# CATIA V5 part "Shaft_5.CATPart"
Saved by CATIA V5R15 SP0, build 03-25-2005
Part number: Shaft_5
Bounding box of the stored display mesh (mm): x -23.8 to 23.8, y -23.8 to 23.8, z 0 to 395
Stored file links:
  E:\#01 CATIA Lecture Materials\#06 DMU\#11 DMU Page01 KIN EX11\Shaft_5.CATPart
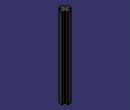
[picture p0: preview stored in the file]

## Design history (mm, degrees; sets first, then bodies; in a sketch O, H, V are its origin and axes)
Body1 (main body)
  Sketch1 on xy-plane, origin (0, 0, 0), H (1, 0, 0), V (0, 1, 0)
    arc A1 centre (0, 0) radius 23.8 from (21.9289, -9.25) to (21.9289, 9.25) ccw
    line L1 (-21.9289, 9.25) -> (-9.25, 9.25)
    line L2 (21.9289, -9.25) -> (9.25, -9.25)
    line L3 (9.25, 21.9289) -> (9.25, 9.25)
    line L4 (-9.25, -21.9289) -> (-9.25, -9.25)
    point P4 (-9.25, -21.9289)
    arc A2 centre (0, 0) radius 23.8 from (-9.25, -21.9289) to (9.25, -21.9289) ccw
    point P6 (-21.9289, 9.25)
    arc A3 centre (0, 0) radius 23.8 from (-21.9289, 9.25) to (-21.9289, -9.25) ccw
    point P8 (9.25, 21.9289)
    arc A4 centre (0, 0) radius 23.8 from (9.25, 21.9289) to (-9.25, 21.9289) ccw
    point P9 (-9.25, 9.25)
    line L5 (9.25, 9.25) -> (21.9289, 9.25)
    line L6 (9.25, -9.25) -> (9.25, -21.9289)
    line L7 (-9.25, 9.25) -> (-9.25, 21.9289)
    point P12 (-9.25, -9.25)
    line L8 (-9.25, -9.25) -> (-21.9289, -9.25)
    radius A1 = 23.8
    distance L1 L2 = 18.5
    distance H L1 = 9.25
    distance L3 L4 = 18.5
    distance V L3 = 9.25
    horizontal: L1 H, L2 H, L5 H, L8 H
    vertical: L3 V, L4 V, L6 V, L7 V
    coincidence: A1 P4, A1 A2, A1 P6, A1 A3, A1 P8, A1 A4, L4 P9, L1 L5, L3 L6, L2 P12, L4 L7, L2 L8
  Pad1: profile Sketch1, direction (0, 0, 1), length 395
  Fillet1: radius 2, on edge [face of Pad1 | face of Pad1] (x4)
  Fillet2: radius 2, on face of Pad1 (x2)
  Fillet3: radius 2, on edge [face of Pad1 from Sketch1.L5 | face of Pad1 from Sketch1.A1]; edge [face of Pad1 from Sketch1.A4 | face of Pad1 from Sketch1.L3]; edge [face of Pad1 from Sketch1.L7 | face of Pad1 from Sketch1.A4]; edge [face of Pad1 from Sketch1.A1 | face of Pad1 from Sketch1.L2]; edge [face of Pad1 from Sketch1.L6 | face of Pad1 from Sketch1.A2]; edge [face of Pad1 from Sketch1.A2 | face of Pad1 from Sketch1.L4]; edge [face of Pad1 from Sketch1.L8 | face of Pad1 from Sketch1.A3]; edge [face of Pad1 from Sketch1.A3 | face of Pad1 from Sketch1.L1]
